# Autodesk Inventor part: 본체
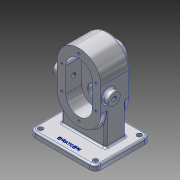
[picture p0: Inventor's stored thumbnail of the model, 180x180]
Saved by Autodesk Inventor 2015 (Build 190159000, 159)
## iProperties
Created: 2020-09
Part Number: 본체
Material: 알루미늄 6061
Document SubType Name: Modeling
Designer: LINEART-A501
Density: 2.7 g/cm^3
Appearance: 알루미늄 - 평지
Mass: 1440.46 g
Surface Area: 785.636 cm^2
Volume: 533.505 cm^3
Author: LINEART-A501
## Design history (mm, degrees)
sketch "스케치1"
  geometry: L1 (40, 62)-(-40, 62); L2 (-40, 62)-(-40, -62); L3 (-40, -62)-(40, -62); L4 (40, -62)-(40, 62); L5 (40, 62)-(-40, -62); L6 (-40, 62)-(40, -62); 1 further point
  constraints: 12 end point, 2 midpoint, 2 parallel, 1 horizontal, 1 perpendicular
  dimensions: "d0" = 80 distance of L3.end L2.end; "d1" = 124 distance of L2.end L1.end
extrude "돌출1" new body sketch "스케치1" distance "d2" = 53; taper "d3" = 0 deg
fillet "모깎기1" dims "d4" = 40
sketch "스케치2"
  geometry: L1 (0, 22)-(0, -22); L2 (-24, 22)-(-24, -22); L3 (24, -22)-(24, 22); L4 (0, 22)-(44, 22); A1 r 40 centre (0, 22) between (40, 22) and (-40, 22) reference; A2 r 24 centre (0, 22) between (24, 22) and (-24, 22); A3 r 24 centre (0, -22) between (-24, -22) and (24, -22); 2 further points
  constraints: 10 end point, 4 point on circle, 4 tangent, 2 centre point, 1 horizontal, 1 midpoint, 1 parallel, 1 perpendicular, 1 vertical
  dimensions: "d5" = 44 distance of L1.start L1.end; "d6" = 90 deg angle of L1 L4 (derived); "d7" = 48 diameter of A3
extrude "돌출2" cut sketch "스케치2" distance "d8" = 29; taper "d9" = 0 deg
sketch "스케치3"
  geometry: A1 r 24 centre (0, 22) between (24, 22) and (-24, 22) reference; A2 r 24 centre (0, -22) between (-24, -22) and (24, -22) reference; 3 further points
  constraints: 2 coincident
hole "구멍1" sketch "스케치3" at (0, 22), (0, -22) diameter "d10" = 25; stored, may be unused: countersink angle "d14" = 90 deg, drill point angle "d16" = 0 deg; dims "d11" = 6, "d12" = 4, "d13" = 2, "d15" = 15
chamfer "모따기1" distance "d17" = 1; stored, may be unused: second distance "d18" = 2, angle "d19" = 45 deg
sketch "스케치4"
  geometry: C1 r 12.5 at (0, 22) reference; C2 r 19 at (0, 22); 1 further point
  constraints: 1 centre point, 1 coincident
  dimensions: "d20" = 38 diameter of C2
extrude "돌출3" join sketch "스케치4" distance "d21" = 17; taper "d22" = 0 deg
sketch "스케치5"
  geometry: L1 (3, -17)-(41, -17) reference; L2 (22, -17)-(36, -17); L3 (22, -17)-(36, -17); L4 (36, -17)-(36, -10.2); L5 (35.5, -9.7)-(30.5, -9.7); L6 (62, 0)-(22, 0) reference; L7 (30.5, -9.7)-(30.5, 9); L8 (34.5, 9)-(9.5, 9) reference; L9 (30.5, 9)-(22, 9); L10 (30.5, 9)-(39, 9); L11 (22, 9)-(22, -17); L12 (22, -17)-(36, -17); A1 r 0.5 centre (35.5, -10.2) between (36, -10.2) and (35.5, -9.7); 2 further points
  constraints: 18 end point, 4 collinear, 3 perpendicular, 3 point on line, 2 horizontal, 2 point on circle, 2 tangent, 1 centre point, 1 midpoint, 1 parallel
  dimensions: "d38" = 14 distance of L2.start L2.end; "d39" = 0 distance between parallel lines of L2 L3 (derived); "d40" = 7.3 distance of L2.end point (36, -9.7); "d41" = 90 deg angle of L4 L2 (derived); "d42" = 5.5 distance of point (36, -9.7) L5.end; "d43" = 90 deg angle of L5 L4 (derived); "d44" = 8.5 distance of L7.end L9.end; "d45" = 180 deg angle of L9 L10 (derived); "d47" = 0.5 radius of A1
revolve "회전1" sketch "스케치5" stored, may be unused: angle "d46" = 90 deg
chamfer "모따기3" distance "d48" = 0.7; stored, may be unused: second distance "d49" = 2, angle "d50" = 30 deg
sketch "스케치6"
  geometry: C1 r 8.5 at (0, 22) reference; C2 r 13.5 at (0, -22) reference; 3 further points
  constraints: 2 vertical alignment
  dimensions: "d51" = 31 distance of C1.centre point (0, 53); "d59" = 31 distance of point (0, -53) C2.centre
hole "구멍3" sketch "스케치6" at (0, 53), (0, -53) diameter "d52" = 4.134; stored, may be unused: countersink angle "d56" = 90 deg, drill point angle "d58" = 118 deg; dims "d53" = 10, "d54" = 4, "d55" = 2, "d57" = 12
sketch "스케치7"
  geometry: C1 r 8.5 at (0, 22) reference; 3 further points
  constraints: 2 horizontal alignment
  dimensions: "d60" = 31 distance of point (-31, 22) C1.centre; "d71" = 31 distance of point (31, 22) C1.centre
hole "구멍4" sketch "스케치7" at (-31, 22), (31, 22) diameter "d61" = 4.134; stored, may be unused: countersink angle "d65" = 90 deg, drill point angle "d67" = 118 deg; dims "d62" = 10, "d63" = 4, "d64" = 2, "d66" = 12
sketch "스케치8"
  geometry: L1 (0, 0)-(0, 44) reference; L2 (-53, 0)-(-53, 44) reference; C1 r 11 at (-39, 22); 2 further points
  constraints: 1 centre point, 1 horizontal alignment, 1 midpoint
  dimensions: "d72" = 22 diameter of C1; "d73" = 14 distance from line of C1.centre L2
extrude "돌출4" join sketch "스케치8" distance "d74" = 10; taper "d75" = 0 deg
hole "구멍5" diameter "d78" = 8.376; stored, may be unused: countersink angle "d82" = 90 deg, drill point angle "d84" = 0 deg; dims "d76" = 10, "d77" = 10, "d79" = 20, "d80" = 4, "d81" = 2, "d83" = 27.3
fillet "모깎기3" dims "d85" = 3
node "작업 평면1"
sketch "스케치9"
  geometry: L1 (0, 0)-(0, 33); L2 (0, 0)-(33, 0); L3 (60, 83)-(-60, 83); L4 (-60, 83)-(-60, -17); L5 (-60, -17)-(60, -17); L6 (60, -17)-(60, 83); L7 (60, 83)-(-60, -17); L8 (-60, 83)-(60, -17)
  constraints: 16 end point, 2 horizontal, 2 midpoint, 2 parallel, 2 perpendicular, 1 vertical
  dimensions: "d87" = 33 distance of L1.start L1.end; "d88" = 90 deg angle of L2 L1 (derived); "d89" = 120 distance of L5.end L4.end; "d90" = 100 distance of L4.end L3.end
extrude "돌출5" join sketch "스케치9" distance "d91" = 10; taper "d92" = 0 deg
fillet "모깎기4" dims "d93" = 10
sketch "스케치10"
  geometry: A1 r 10 centre (-50, -73) between (-60, -73) and (-50, -83) reference; 2 further points
  constraints: 1 coincident
hole "구멍6" sketch "스케치10" at (-50, -73) diameter "d94" = 9; stored, may be unused: countersink angle "d98" = 90 deg, drill point angle "d100" = 0 deg; dims "d95" = 20, "d96" = 4, "d97" = 2, "d99" = 27.3
fillet "모깎기5" dims "d107" = 3
sketch "스케치11"
  geometry: L1 (-60, 7)-(-60, -73) reference; L2 (-50, -83)-(50, -83) reference; 2 further points
  constraints: 1 other
  dimensions: "d108" = 60 distance from line of point (0, -71) L1; "d109" = 12 distance from line of L2 point (0, -71)
feature "엠보싱1" sketch "스케치11" dims "d0" = 80, "d1" = 124, "d5" = 44, "d6" = 90 deg (derived), "d7" = 48, "d110" = 0.5, "d111" = 0
sketch "스케치12"
  geometry: L1 (-90, -17)-(-90, 8); L2 (-90, -7)-(-90, 73) reference; L3 (-90, 8)-(-60, 8); L4 (-90, 8)-(-60, 8); L5 (-60, 8)-(-60, 45); L6 (-60, 45)-(-90, 45); L7 (-90, 45)-(-90, 8); 1 further point
  constraints: 12 end point, 2 horizontal, 2 perpendicular, 1 collinear, 1 point on line
  dimensions: "d112" = 25 distance of L1.start L1.end; "d113" = 30 distance of L1.end L3.end; "d114" = 0 distance between parallel lines of L3 L4 (derived); "d115" = 37 distance of L3.end L5.end; "d116" = 90 deg angle of L5 L3 (derived); "d117" = 30 distance of L5.end L6.end; "d118" = 90 deg angle of L6 L5 (derived)
extrude "돌출6" join sketch "스케치12" stored distance "d119" = 80; taper "d120" = 0 deg
sketch "스케치13"
  geometry: L1 (0, 20)-(0, 58); L2 (0, 20)-(27.51, 20); L3 (80, 20)-(80, 58); L4 (80, 20)-(52.49, 20); L5 (52.49, 20)-(80, 20) reference; A1 r 40 centre (40, 58) between (0, 58) and (80, 58) reference; A2 r 40 centre (40, 58) between (0, 58) and (27.51, 20); A3 r 40 centre (40, 58) between (52.49, 20) and (80, 58); 1 further point
  constraints: 8 end point, 6 point on circle, 3 tangent, 2 centre point, 2 concentric, 2 vertical, 1 collinear, 1 perpendicular
extrude "돌출7" join sketch "스케치13" distance "d121" = 37; taper "d122" = 0 deg
fillet "모깎기6" dims "d123" = 3
fillet "모깎기7" dims "d124" = 3
node "솔리드1"
pattern_linear "직사각형 패턴1" dims "d70" = 44
mirror "대칭1"
pattern_linear "직사각형 패턴2" dims "d103" = 100
